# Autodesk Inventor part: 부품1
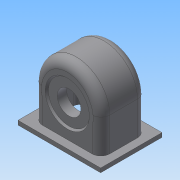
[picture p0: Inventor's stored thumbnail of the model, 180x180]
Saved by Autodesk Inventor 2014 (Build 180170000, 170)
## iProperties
Created: 2016-01
Part Number: 부품1
Material: Generic
Document SubType Name: Modeling
Designer: User
Density: 1 g/cm^3
Appearance: Default
Author: User
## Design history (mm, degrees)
sketch "스케치1"
  geometry: L1 (-57, 0)-(57, 0); L2 (57, 0)-(57, -64); L3 (57, -64)-(-57, -64); L4 (-57, -64)-(-57, 0); C1 r 57 at (0, 0); 2 further points
  constraints: 8 end point, 2 coincident, 2 parallel, 1 centre point, 1 horizontal, 1 midpoint, 1 perpendicular
  dimensions: "d0" = 114 diameter of C1; "d1" = 114 distance of L2.end L3.end; "d2" = 64 distance of L1.end L2.end
extrude "돌출1" new body sketch "스케치1" stored distance "d3" = 77; taper "d4" = 0 deg
feature "쉘1" dims "d7" = 6
sketch "스케치3"
  geometry: L1 (114, 0)-(114, -77) reference; L2 (0, 0)-(114, 0) reference; L3 (0, 0)-(0, -77) reference; L4 (114, -77)-(0, -77) reference; L5 (-13, 13.5)-(127, 13.5); L6 (127, 13.5)-(127, -90.5); L7 (127, -90.5)-(-13, -90.5); L8 (-13, -90.5)-(-13, 13.5); L9 (-13, 13.5)-(127, -90.5); 2 further points
  constraints: 10 end point, 2 parallel, 1 coincident, 1 horizontal, 1 midpoint, 1 perpendicular
  dimensions: "d8" = 140 distance of L5.start L5.end; "d9" = 104 distance of L7.end L5.start
extrude "돌출2" join sketch "스케치3" distance "d10" = 7; taper "d11" = 0 deg
fillet "모깎기1" dims "d12" = 15
fillet "모깎기2" dims "d13" = 9
sketch "스케치5"
  geometry: L1 (-64, 52)-(-57, 52) reference; L2 (-57, 52)-(-57, 38.5) reference; L3 (-57, 38.5)-(42, 38.5) reference; L4 (57, 23.5)-(57, -23.5) reference; L5 (42, -38.5)-(-57, -38.5) reference; L6 (-57, -38.5)-(-57, -52) reference; L7 (-57, -52)-(-64, -52) reference; L8 (-64, -52)-(-64, -32.5) reference; L9 (-64, -32.5)-(42, -32.5) reference; L10 (51, -23.5)-(51, 23.5) reference; L11 (42, 32.5)-(-64, 32.5) reference; L12 (-64, 32.5)-(-64, 52) reference; L13 (-4, 38.5)-(-4, -38.5); L14 (16, 35.5)-(16, 19.5); L15 (30.899, 35.5)-(-4, 35.5); L16 (24, 19.5)-(16, 19.5); L17 (24, 38.5)-(24, 19.5); L18 (24, 19.5)-(39.943, 38.5); L19 (30.899, 35.5)-(33.416, 38.5); L20 (33.416, 38.5)-(39.943, 38.5); L21 (0, 38.5)-(42, 38.5) reference; L22 (-4, 38.5)-(33.416, 38.5); L23 (-4, 32.5)-(16, 32.5); L24 (16, 32.5)-(16, 35.5); L25 (16, 35.5)-(-4, 35.5); L26 (-4, 35.5)-(-4, 32.5); L27 (-4, 38.5)-(-4, 35.5); L28 (30.899, 35.5)-(-4, 35.5); A1 r 15 centre (42, 23.5) between (57, 23.5) and (42, 38.5) reference; A2 r 15 centre (42, -23.5) between (42, -38.5) and (57, -23.5) reference; A3 r 9 centre (42, -23.5) between (42, -32.5) and (51, -23.5) reference; A4 r 9 centre (42, 23.5) between (51, 23.5) and (42, 32.5) reference; 1 further point
  constraints: 30 end point, 9 point on line, 7 parallel, 4 collinear, 2 perpendicular, 1 horizontal
  dimensions: "d22" = 60 distance between parallel lines of L12 L13; "d23" = 40 diameter of L14 L13; "d24" = 3 distance between parallel lines of L15 L3; "d25" = 19 distance between parallel lines of L16 L3; "d26" = 56 diameter of L17 L13; "d27" = 50 deg angle of L16 L18; "d30" = 5 distance between parallel lines of L19 L18
  node "절단 모서리 투영2"
revolve "회전1" stored, may be unused: angle "d31" = 90 deg
revolve "회전2" stored, may be unused: angle "d32" = 90 deg
node "솔리드1"
other parameters: "d29" = 5
